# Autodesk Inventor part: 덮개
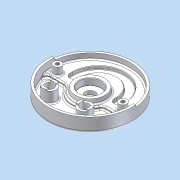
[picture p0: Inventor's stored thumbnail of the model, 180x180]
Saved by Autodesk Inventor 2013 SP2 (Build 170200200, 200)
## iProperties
Company: 한국ATC센터
Created: 2015-04
Part Number: 덮개
Document SubType Name: Modeling
Designer: KYOUNG IL JANG
Density: 2.71 g/cm^3
Material: 알루미늄-6061
Author: KYOUNG IL JANG
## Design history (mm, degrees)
sketch "스케치1"
  geometry: L1 (-59, -19)-(-59, 19); L2 (59, 19)-(59, -19); L3 (-41, 19)-(-41, -19); L4 (41, -19)-(41, 19); L5 (59, 5)-(41, 5); L6 (-41, 5)-(-59, 5); C1 r 90 at (0, 0); C2 r 95 at (0, 0); A1 r 59 centre (0, 19) between (59, 19) and (-59, 19); A2 r 59 centre (0, -19) between (-59, -19) and (59, -19); A3 r 41 centre (0, -19) between (-41, -19) and (41, -19); A4 r 41 centre (0, 19) between (41, 19) and (-41, 19); 2 further points
  constraints: 12 end point, 8 point on circle, 6 centre point, 4 point on line, 4 tangent, 2 parallel, 2 perpendicular, 1 coincident, 1 collinear, 1 horizontal alignment, 1 midpoint, 1 vertical, 1 vertical alignment, 3 other
  dimensions: "d2" = 180 diameter of C1; "d3" = 156 dimension on A2 A1; "d4" = 118 distance between parallel lines of L2 L1; "d5" = 18 distance between parallel lines of L2 L4; "d8" = 190 diameter of C2; "d121" = 5 distance from line of L5 point (0, 0)
extrude "돌출1" new body sketch "스케치1" distance "d6" = 14; taper "d7" = 0 deg
extrude "돌출2" join sketch "스케치1" distance "d9" = 13; taper "d10" = 0 deg
extrude "돌출3" cut sketch "스케치1" distance "d11" = 7; taper "d12" = 0 deg
sketch "스케치2"
  geometry: C1 r 11.5 at (0, 0); 1 further point
  constraints: 1 centre point, 1 coincident
  dimensions: "d13" = 23 diameter of C1
extrude "돌출4" cut sketch "스케치2" stored distance "d14" = 7; taper "d15" = 0 deg
fillet "모깎기1"
fillet "모깎기2"
sketch "스케치3"
  geometry: L1 (-89.658, 7.844)-(-94.638, 8.28); L2 (89.658, 7.844)-(94.638, 8.28); L3 (0, 0)-(0, -90); A1 r 95 centre (0, 0) between (-94.638, 8.28) and (94.638, 8.28) reference; A2 r 90 centre (0, 0) between (-89.658, 7.844) and (89.658, 7.844) reference; 1 further point
  constraints: 6 end point, 5 point on circle, 1 point on line, 1 vertical, 1 other
  dimensions: "d16" = 190 deg dimension on L2 L1
extrude "돌출5" join sketch "스케치3" distance "d17" = 5; taper "d18" = 0 deg
hole "구멍1" diameter "d21" = 50; stored, may be unused: countersink angle "d25" = 90 deg, drill point angle "d27" = 0 deg; dims "d19" = 10, "d20" = 10, "d22" = 6, "d23" = 4, "d24" = 2, "d26" = 5
fillet "모깎기3" dims "d28" = 0.3
fillet "모깎기5" dims "d30" = 3
sketch "스케치4"
  geometry: C1 r 35 at (0, 0); C2 r 25 at (0, 0); 1 further point
  constraints: 2 centre point, 1 coincident
  dimensions: "d32" = 70 diameter of C1 (derived); "d36" = 10 radial gap between concentric circles of C1 C2
extrude "돌출6" join sketch "스케치4" distance "d33" = 10; taper "d34" = 0 deg
feature "면 기울기2" dims angle "d37" = 10 deg
chamfer "모따기1" distance "d39" = 1; stored, may be unused: second distance "d40" = 2, angle "d41" = 45 deg
fillet "모깎기7" dims "d42" = 5
sketch "스케치5"
  geometry: L1 (-40.249, -12)-(-89.196, -12); L2 (40.249, -12)-(89.196, -12); A1 r 90 centre (0, 0) between (-89.196, -12) and (89.196, -12) reference; A2 r 42 centre (0, 0) between (-40.249, -12) and (40.249, -12); 1 further point
  constraints: 4 end point, 4 point on circle, 1 centre point, 1 collinear, 1 horizontal, 1 point on line
  dimensions: "d43" = 48 radial gap between concentric circles of A1 A2; "d44" = 12 distance from line of point (0, 0) L1
extrude "돌출7" cut sketch "스케치5" stored distance "d45" = 10; taper "d46" = 0 deg
fillet "모깎기8" dims "d47" = 10
chamfer "모따기2" distance "d49" = 1; stored, may be unused: second distance "d50" = 2, angle "d51" = 45 deg
sketch "스케치8"
  geometry: C1 r 9 at (74, 0); C2 r 9 at (-74, 0); A1 r 74 centre (0, 0) between (74, 0) and (-74, 0); 1 further point
  constraints: 3 centre point, 2 horizontal alignment, 2 point on circle, 1 coincident, 1 equal radius
  dimensions: "d64" = 18 diameter of C1; "d65" = 148 diameter of A1
extrude "돌출9" join sketch "스케치8" stored distance "d66" = 5; taper "d67" = 0 deg
sketch "스케치11"
  geometry: C1 r 15 at (40, -52); C2 r 15 at (-40, -52); 1 further point
  constraints: 2 centre point, 1 equal radius, 1 horizontal alignment
  dimensions: "d82" = 52 vertical distance of point (0, 0) C1.centre; "d83" = 30 diameter of C1; "d84" = 80 distance of C2.centre C1.centre; "d85" = 40 horizontal distance of point (0, 0) C1.centre (= 0.5 x d84)
extrude "돌출10" join sketch "스케치11" stored distance "d86" = 10; taper "d87" = 0 deg
node "구멍3"
node "구멍5"
hole "구멍6" diameter "d92" = 20; stored, may be unused: countersink angle "d96" = 90 deg, drill point angle "d98" = 118 deg; dims "d90" = 10, "d91" = 10, "d93" = 6, "d94" = 4, "d95" = 2, "d97" = 8
hole "구멍7" diameter "d101" = 20; stored, may be unused: countersink angle "d105" = 90 deg, drill point angle "d107" = 118 deg; dims "d99" = 10, "d100" = 10, "d102" = 6, "d103" = 4, "d104" = 2, "d106" = 8
fillet "모깎기13" dims "d108" = 3
sketch "스케치13"
  geometry: L1 (-20.252, -58)-(-26, -58); L2 (-42, -58)-(-47.748, -58); L3 (-20.252, -46)-(-26, -46); L4 (-42, -46)-(-47.748, -46); L5 (-108, -65.748)-(-108, -60); L6 (-108, -44)-(-108, -38.252); L7 (-120, -44)-(-120, -38.252); L8 (-120, -60)-(-120, -65.748); A1 r 15 centre (-34, -52) between (-20.252, -58) and (-47.748, -58) reference; A2 r 10 centre (-34, -52) between (-26, -58) and (-42, -58) reference; A3 r 15 centre (-114, -52) between (-108, -65.748) and (-108, -38.252) reference; A4 r 10 centre (-114, -52) between (-108, -60) and (-108, -44) reference; 1 further point
  constraints: 16 end point, 16 point on circle, 3 equal length, 3 point on line, 2 collinear, 1 horizontal, 1 perpendicular
  dimensions: "d114" = 12 distance between parallel lines of L4 L2; "d115" = 6 distance from line of A1.centre L2 (= 0.5 x d114); "d116" = 12 distance between parallel lines of L8 L5 (= d114); "d117" = 6 distance from line of A3.centre L5 (= d115)
extrude "돌출12" join sketch "스케치13" distance "d118" = 3; taper "d119" = 0 deg
fillet "모깎기14" dims "d120" = 1
node "솔리드1"
sketch "스케치9"
  geometry: 1 further point
hole "구멍2" sketch "스케치9" diameter "d68" = 8.376; stored, may be unused: countersink angle "d72" = 90 deg, drill point angle "d74" = 120 deg; dims "d69" = 16, "d70" = 4, "d71" = 2, "d73" = 21
sketch "스케치10"
  geometry: 1 further point
hole "구멍4" sketch "스케치10" diameter "d75" = 8.376; stored, may be unused: countersink angle "d79" = 90 deg, drill point angle "d81" = 120 deg; dims "d76" = 16, "d77" = 4, "d78" = 2, "d80" = 21
